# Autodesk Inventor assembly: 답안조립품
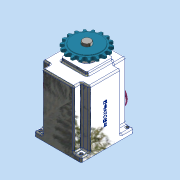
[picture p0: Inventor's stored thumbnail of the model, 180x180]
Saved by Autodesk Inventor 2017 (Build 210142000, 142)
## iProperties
Part Number: 답안조립품
Material: 일반
Document SubType Name: Assembly
Designer: MRC
Author: MRC
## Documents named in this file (16)
- C:\Users\MRC\Desktop\720212V1003\답안조립품.iam
- C:\Users\MRC\Desktop\720212V1003\멈춤나사 M3.ipt
- C:\Users\MRC\Desktop\720212V1003\메인 축.ipt
- C:\Users\MRC\Desktop\720212V1003\베어링 608.ipt
- C:\Users\MRC\Desktop\720212V1003\베어링 6003.ipt
- C:\Users\MRC\Desktop\720212V1003\본체.ipt
- C:\Users\MRC\Desktop\720212V1003\볼트 M4 x 10.ipt
- C:\Users\MRC\Desktop\720212V1003\부시.ipt
- C:\Users\MRC\Desktop\720212V1003\상부 캡.ipt
- C:\Users\MRC\Desktop\720212V1003\서브 축.ipt
- C:\Users\MRC\Desktop\720212V1003\스프로킷.ipt
- C:\Users\MRC\Desktop\720212V1003\슬라이더.ipt
- C:\Users\MRC\Desktop\720212V1003\오일 실 8 x 22 x 7.ipt
- C:\Users\MRC\Desktop\720212V1003\오일 실 17 x 32 x 8.ipt
- C:\Users\MRC\Desktop\720212V1003\커버.ipt
- C:\Users\MRC\Desktop\720212V1003\키 5 x 5.ipt
